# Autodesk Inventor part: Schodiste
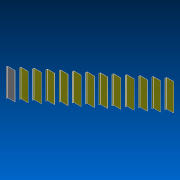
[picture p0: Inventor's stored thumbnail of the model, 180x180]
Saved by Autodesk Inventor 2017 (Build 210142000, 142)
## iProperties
Created: 2016-10
Part Number: Schodiste
Material: Všeobecné
Document SubType Name: Plech
Designer: navara
Density: 1 g/cm^3
Sheet Metal Rule: Výchozí
Appearance: Výchozí
Flat Pattern Width: 28.6694 cm
Flat Pattern Length: 90 cm
Flat Pattern Area: 2580.25 cm^2
Sheet Metal Width: 286,694 mm
Sheet Metal Length: 900,000 mm
Sheet Metal Area: 258024,914 mm^2
Beppe: Schodiste.ipt
Author: navara
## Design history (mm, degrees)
sketch "SkeletonNacrt"
  geometry: L1 (0, 0)-(0, 192.308); L2 (0, 192.308)-(245.385, 192.308); L3 (245.385, 192.308)-(0, 0); L4 (245.385, 192.308)-(245.385, 384.615); L5 (245.385, 384.615)-(490.769, 384.615); L6 (490.769, 384.615)-(490.769, 576.923); L7 (490.769, 576.923)-(736.154, 576.923); L8 (736.154, 576.923)-(736.154, 769.231); L9 (736.154, 769.231)-(981.538, 769.231); L10 (981.538, 769.231)-(981.538, 961.538); L11 (981.538, 961.538)-(1226.923, 961.538); L12 (1226.923, 961.538)-(1226.923, 1153.846); L13 (1226.923, 1153.846)-(1472.308, 1153.846); L14 (1472.308, 1153.846)-(1472.308, 1346.154); L15 (1472.308, 1346.154)-(1717.692, 1346.154); L16 (1717.692, 1346.154)-(1717.692, 1538.462); L17 (1717.692, 1538.462)-(1963.077, 1538.462); L18 (1963.077, 1538.462)-(1963.077, 1730.769); L19 (1963.077, 1730.769)-(2208.462, 1730.769); L20 (2208.462, 1730.769)-(2208.462, 1923.077); L21 (2208.462, 1923.077)-(2453.846, 1923.077); L22 (2453.846, 1923.077)-(2453.846, 2115.385); L23 (2453.846, 2115.385)-(2699.231, 2115.385); L24 (2699.231, 2115.385)-(2699.231, 2307.692); L25 (2699.231, 2307.692)-(2944.615, 2307.692); L26 (2944.615, 2307.692)-(2944.615, 2500); L27 (2944.615, 2500)-(3190, 2500); L28 (0, 0)-(3190, 0); L29 (3190, 0)-(3190, 2500)
  constraints: 58 end point, 2 perpendicular, 1 horizontal, 1 vertical, 61 other
  dimensions: "d0" = 192.30769 distance of L1.start L1.end (= VyskaSchodu); "d1" = 245.38462 distance of L1.end L2.end (= DelkaSchodu); "d2" = 311.7625 distance of L2.end L1.start (derived); "d5" = 311.7625 distance of L1.end L4.end (= d2); "d10" = 3190 distance of L1.start L28.end (= DelkaSchodiste); "d11" = 2500 distance of L28.end L29.end (= VyskaSchodiste)
node "Schodnice"
  sketch "Náčrt2"
    geometry: L1 (0, 0)-(0, 192.308) reference; L2 (0, 192.308)-(245.385, 192.308) reference; L3 (0, 142.308)-(0, 192.308); L4 (0, 192.308)-(245.385, 192.308)
    constraints: 4 end point, 1 collinear, 1 point on line
    dimensions: "d12" = 50 distance of L3.start L1.end (= VelikostLemu)
node "SmerStoupaniSchodu"
pattern_linear "Schodiste" dims "d25" = 311.7625 (= d2)
node "Definice strany A"
node "Těleso1"
feature "Deska1" dims "d13" = 5 (= ŠířkaVýštipu), "d14" = 2.5 (= HloubkaVýštipu), "d15" = 10 (= MinimálníZbytek), "d16" = 5 (= PoloměrOhybu), "d17" = 900 (= SirkaSchodnice), "d18" = 5 (= PoloměrOhybu), "d19" = 0.5, "d20" = 20 (= VelikostRohovéhoVýštipu), "d21" = 5 (= VelikostMezery), "d22" = 5 (= VelikostJacobihoPoloměru), "Tloušťka" = 5 (derived), "MezeraVystřižení" = 0.01
feature "Ohyb1" dims "d13" = 5 (= ŠířkaVýštipu), "d14" = 2.5 (= HloubkaVýštipu), "d15" = 10 (= MinimálníZbytek), "d16" = 5 (= PoloměrOhybu), "d18" = 5 (= PoloměrOhybu), "d19" = 0.5, "Tloušťka" = 5 (derived), "MezeraVystřižení" = 0.01
feature "Roh1" dims "d19" = 0.5, "d20" = 20 (= VelikostRohovéhoVýštipu), "d21" = 5 (= VelikostMezery), "d22" = 5 (= VelikostJacobihoPoloměru)
feature "Definice1"
other parameters: "VyskaSchodiste" = 2500 [user parameter; used in 2 equation terms], "DelkaSchodiste" = 3190 (computed from DelkaSchodu, PocetSchodu) [user parameter; used in 1 equation term], "VyskaSchodu" = 192.30769 (computed from VyskaSchodiste, PocetSchodu) [user parameter; used in 2 equation terms], "DelkaSchodu" = 245.38462 (computed from VyskaSchodu) [user parameter; used in 2 equation terms], "VelikostLemu" = 50 [user parameter; used in 1 equation term], "KSoučinitel" = 4.4, "PoloměrOhybu" = 5 (= Tloušťka), "ŠířkaVýštipu" = 5 (= Tloušťka), "HloubkaVýštipu" = 2.5 (= 0.5 x Tloušťka), "PřechodovýPoloměr" = 5 (= PoloměrOhybu), "VelikostJacobihoPoloměru" = 5 (= Tloušťka), "VelikostMezery" = 5 (= Tloušťka), "DelkaSchodu" = 245.38462, "VyskaSchodu" = 192.30769, "HloubkaVýštipu" = 2.5, "PoloměrOhybu" = 5, "PřechodovýPoloměr" = 5, "Tloušťka" = 5, "VelikostJacobihoPoloměru" = 5, "VelikostMezery" = 5, "ŠířkaVýštipu" = 5
